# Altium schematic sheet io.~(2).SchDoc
size Letter
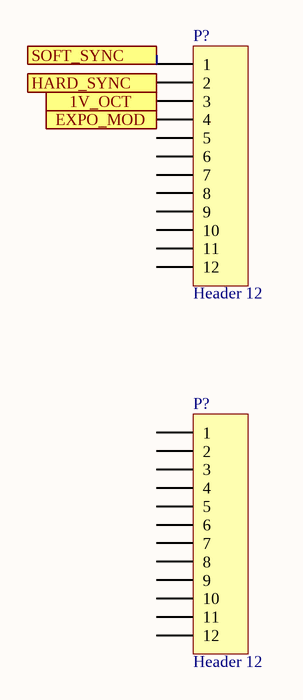
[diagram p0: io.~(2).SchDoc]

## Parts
(Parts that share a designator on the sheet are numbered #1, #2 ... from top to bottom, then left to right.)
P?#1  Header 12  [HDR1X12]
P?#2  Header 12  [HDR1X12]

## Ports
1V_OCT, EXPO_MOD, HARD_SYNC, SOFT_SYNC

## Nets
1V_OCT: P?#1.3 ; port 1V_OCT
EXPO_MOD: P?#1.4 ; port EXPO_MOD
HARD_SYNC: P?#1.2 ; port HARD_SYNC
SOFT_SYNC: P?#1.1 ; port SOFT_SYNC

Not connected (* = marked no-connect by the designer): P?#1 5 6 7 8 9 10 11 12; P?#2 1 2 3 4 5 6 7 8 9 10 11 12

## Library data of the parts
P?#1 P?#2 = Header 12: Header, 12-Pin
